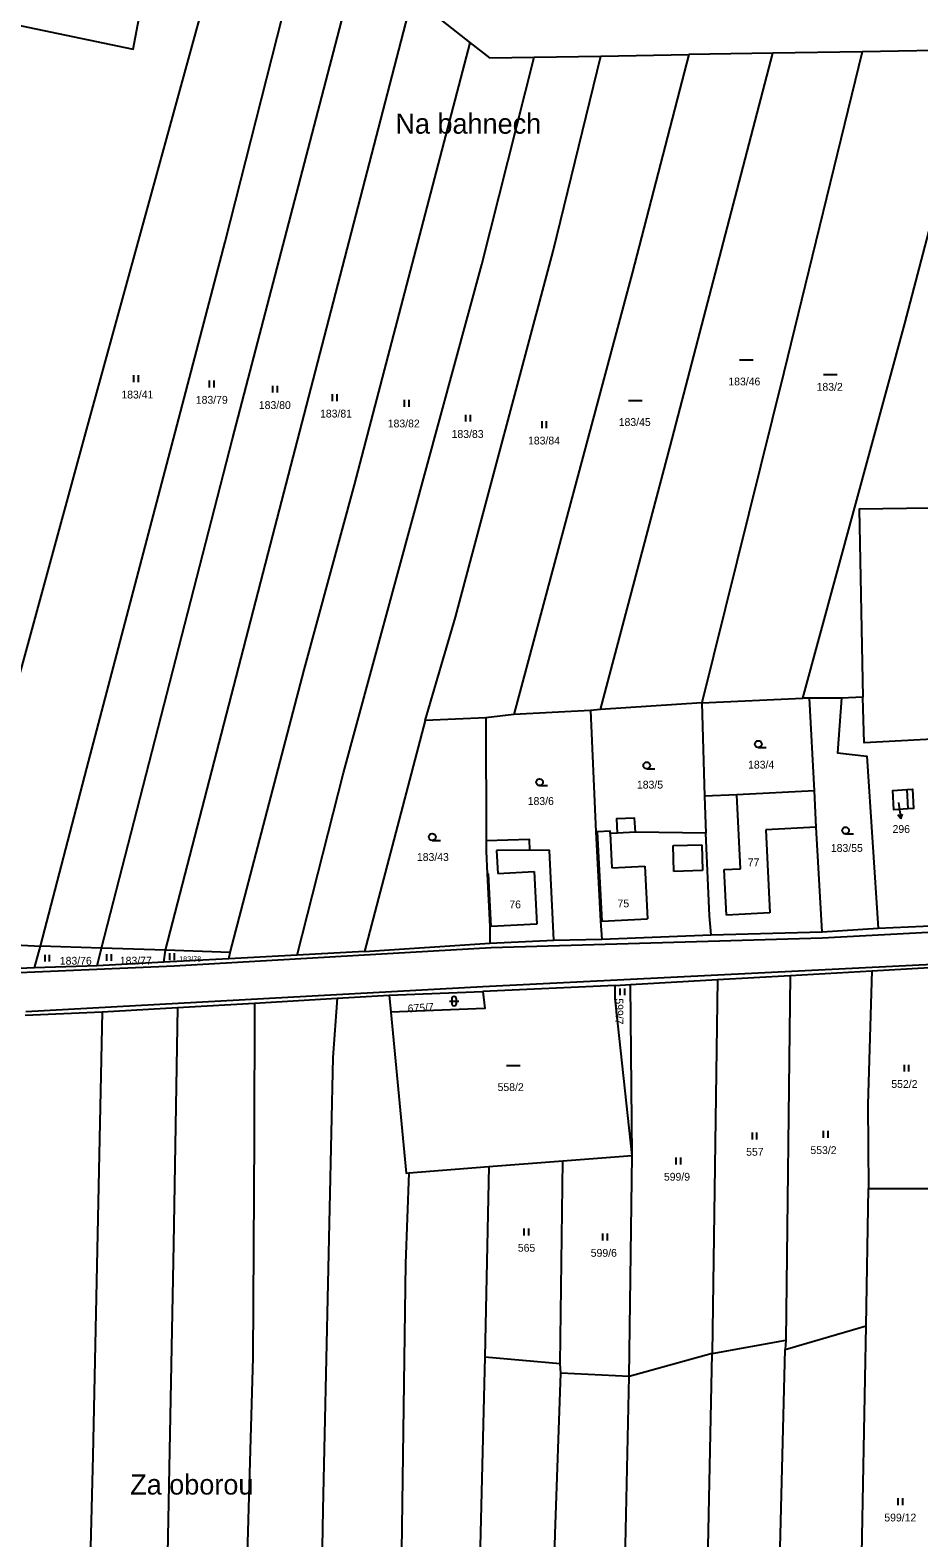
# Model space of a CAD drawing. Extents: x -747333 to -743907, y -1134120 to -1130051.
# Drawn here: x -747026.2 to -746832.8, y -1132407.1 to -1132079.1 of the extents above; entities that cross this region are included whole.
import ezdxf

# ---------------------------------------------------------------- set-up
doc = ezdxf.new("R2010")
doc.units = 0
for name, color, linetype in [('Hranice parcel', 7, 'Continuous'), ('Parcelní čísla', 7, 'Continuous'), ('Pop  PČ popisy', 7, 'Continuous'), ('Vnitřní kresba', 7, 'Continuous'), ('Značky kultur', 7, 'Continuous')]:
    doc.layers.add(name, color=color, linetype=linetype)

msp = doc.modelspace()

# ---------------------------------------------------------------- linework, layer by layer
at = {"layer": 'Hranice parcel'}
for p, q in [((-746942.98, -1132071.88), (-746930.38, -1132081.81)), ((-746916.47, -1132084.95), (-746901.96, -1132084.72)), ((-746901.96, -1132084.72), (-746882.82, -1132084.41)), ((-746864.54, -1132084.11), (-746882.82, -1132084.41)), ((-746845.06, -1132083.8), (-746864.54, -1132084.11)), ((-746820.24, -1132083.39), (-746845.06, -1132083.8)), ((-746879.98, -1132225.48), (-746902.04, -1132226.9)), ((-746879.98, -1132225.48), (-746858.02, -1132224.47)), ((-746879.98, -1132225.48), (-746879.44, -1132245.79)), ((-746856.57, -1132224.4), (-746858.02, -1132224.47)), ((-746849.62, -1132224.47), (-746856.57, -1132224.4)), ((-746855.47, -1132244.6), (-746856.57, -1132224.4)), ((-746844.91, -1132224.19), (-746849.62, -1132224.47)), ((-746940.23, -1132229.26), (-746953.39, -1132279.59)), ((-746927.02, -1132228.69), (-746940.23, -1132229.26)), ((-746920.89, -1132228), (-746927.02, -1132228.69)), ((-746927.02, -1132228.69), (-746926.95, -1132255.46)), ((-746904.25, -1132227.12), (-746920.89, -1132228)), ((-746902.04, -1132226.9), (-746904.25, -1132227.12)), ((-746904.25, -1132227.12), (-746903.04, -1132253.55)), ((-746879.44, -1132245.79), (-746879.09, -1132253.81)), ((-746926.95, -1132255.46), (-746926.94, -1132257.7)), ((-746903.04, -1132253.55), (-746902.06, -1132272.95)), ((-746879.09, -1132253.81), (-746894.45, -1132253.61)), ((-746926.15, -1132274.1), (-746926.09, -1132277.74)), ((-746902.06, -1132272.95), (-746901.75, -1132276.88)), ((-746877.98, -1132275.95), (-746853.79, -1132275.31)), ((-746853.79, -1132275.31), (-746841.63, -1132274.45)), ((-746841.63, -1132274.45), (-746801.64, -1132272.79)), ((-747044.43, -1132277.24), (-747023.94, -1132278.4)), ((-747025.21, -1132283.12), (-747023.94, -1132278.4)), ((-747010.67, -1132278.83), (-747023.94, -1132278.4)), ((-747011.61, -1132282.68), (-747010.67, -1132278.83)), ((-746996.68, -1132279.26), (-747010.67, -1132278.83)), ((-746953.39, -1132279.59), (-746926.09, -1132277.74)), ((-746926.09, -1132277.74), (-746912.17, -1132277.09)), ((-746912.17, -1132277.09), (-746901.75, -1132276.88)), ((-746901.75, -1132276.88), (-746877.98, -1132275.95)), ((-746997.1, -1132281.91), (-747011.61, -1132282.68)), ((-746997.1, -1132281.91), (-746996.68, -1132279.26)), ((-746982.92, -1132281.16), (-746997.1, -1132281.91)), ((-746982.63, -1132279.76), (-746996.68, -1132279.26)), ((-746982.92, -1132281.16), (-746982.63, -1132279.76)), ((-746968.03, -1132280.37), (-746982.92, -1132281.16)), ((-746953.39, -1132279.59), (-746968.03, -1132280.37)), ((-747025.21, -1132283.12), (-747046, -1132283.98)), ((-747011.61, -1132282.68), (-747025.21, -1132283.12)), ((-746876.61, -1132285.67), (-746860.79, -1132284.76)), ((-746860.79, -1132284.76), (-746861.69, -1132364.09)), ((-746860.79, -1132284.76), (-746843.01, -1132283.74)), ((-746843.01, -1132283.74), (-746826.69, -1132282.8)), ((-746948.06, -1132289.05), (-746927.67, -1132288.23)), ((-746898.83, -1132286.94), (-746927.67, -1132288.23)), ((-746898.83, -1132286.94), (-746895.48, -1132286.75)), ((-746895.48, -1132286.75), (-746876.61, -1132285.67)), ((-746895.12, -1132323.92), (-746895.48, -1132286.75)), ((-746876.61, -1132285.67), (-746877.7, -1132367.03)), ((-747010.5, -1132292.69), (-746994.07, -1132291.76)), ((-746994.07, -1132291.76), (-746977.35, -1132290.83)), ((-746977.35, -1132290.83), (-746959.35, -1132289.69)), ((-746959.35, -1132289.69), (-746948.06, -1132289.05)), ((-746948.06, -1132289.05), (-746947.65, -1132292.79)), ((-747027.28, -1132293.41), (-747010.5, -1132292.69)), ((-746910.26, -1132325.11), (-746895.12, -1132323.92)), ((-746895.83, -1132372.03), (-746895.12, -1132323.92)), ((-746943.76, -1132327.73), (-746926.33, -1132326.33)), ((-746926.33, -1132326.33), (-746927.19, -1132367.73)), ((-746926.33, -1132326.33), (-746910.26, -1132325.11)), ((-746910.84, -1132369.17), (-746910.26, -1132325.11)), ((-746844.2, -1132361.04), (-746843.71, -1132331.14)), ((-746843.71, -1132331.14), (-746827.45, -1132331.11)), ((-746861.83, -1132366.16), (-746844.2, -1132361.04)), ((-746877.7, -1132367.03), (-746861.69, -1132364.09)), ((-746861.69, -1132364.09), (-746861.83, -1132366.16)), ((-746877.7, -1132367.03), (-746895.83, -1132372.03)), ((-746927.19, -1132367.73), (-746910.84, -1132369.17)), ((-746910.7, -1132371.31), (-746910.84, -1132369.17)), ((-746895.83, -1132372.03), (-746910.7, -1132371.31))]:
    msp.add_line(p, q, dxfattribs=at)
for points in [[(-747023.94, -1132278.4), (-747013.85, -1132239.65), (-746995.01, -1132168), (-746983.73, -1132125.17), (-746965.7, -1132053.97)], [(-746983.8, -1132056.28), (-747014.12, -1132166.6), (-747033.2, -1132236.24)], [(-747029.81, -1132077.77), (-747003.78, -1132083.21), (-746998.74, -1132056.7)], [(-747010.67, -1132278.83), (-746982.16, -1132168), (-746954.65, -1132062.68)], [(-746996.68, -1132279.26), (-746973.89, -1132190.98), (-746953.76, -1132113.62), (-746942.98, -1132071.88)], [(-746982.63, -1132279.76), (-746966.54, -1132218.25), (-746955.56, -1132178), (-746930.38, -1132081.81)], [(-746930.38, -1132081.81), (-746926.2, -1132085.11), (-746916.47, -1132084.95)], [(-746968.03, -1132280.37), (-746957.98, -1132240.67), (-746927.88, -1132130.04), (-746916.47, -1132084.95)], [(-746940.23, -1132229.26), (-746933.58, -1132206.84), (-746912.31, -1132127.19), (-746901.96, -1132084.72)], [(-746882.82, -1132084.41), (-746895.12, -1132131.95), (-746920.89, -1132228)], [(-746902.04, -1132226.9), (-746886.87, -1132169.67), (-746864.54, -1132084.11)], [(-746845.06, -1132083.8), (-746862.13, -1132153.61), (-746879.98, -1132225.48)], [(-746858.02, -1132224.47), (-746835.83, -1132142.89), (-746820.24, -1132083.39)], [(-746825.13, -1132182.99), (-746845.75, -1132183.3), (-746844.91, -1132224.19)], [(-746849.62, -1132224.47), (-746850.48, -1132236.32), (-746844.05, -1132237.04), (-746841.63, -1132274.45)], [(-746794.52, -1132231.47), (-746844.62, -1132234.18), (-746844.91, -1132224.19)], [(-746855.47, -1132244.6), (-746872.39, -1132245.44), (-746879.44, -1132245.79)], [(-746853.79, -1132275.31), (-746855.08, -1132252.52), (-746855.47, -1132244.6)], [(-746835.13, -1132248.54), (-746838.17, -1132248.72), (-746838.41, -1132244.5), (-746835.37, -1132244.32), (-746834.14, -1132244.25), (-746833.89, -1132248.47), (-746835.13, -1132248.54)], [(-746894.45, -1132253.61), (-746894.61, -1132250.52), (-746898.59, -1132250.72), (-746898.44, -1132253.81), (-746899.93, -1132253.89), (-746899.95, -1132253.39), (-746902.74, -1132253.53), (-746903.04, -1132253.55)], [(-746912.17, -1132277.09), (-746913.17, -1132257.6), (-746917.39, -1132257.53), (-746917.46, -1132255.18), (-746926.95, -1132255.46)], [(-746877.98, -1132275.95), (-746878.29, -1132271.82), (-746879.09, -1132253.81)], [(-746926.94, -1132257.7), (-746926.7, -1132262.67), (-746926.15, -1132274.1)], [(-746843.01, -1132283.74), (-746843.82, -1132312.84), (-746843.71, -1132331.14)], [(-746927.67, -1132288.23), (-746927.23, -1132291.94), (-746947.65, -1132292.79)], [(-746895.12, -1132323.92), (-746898.83, -1132289.8), (-746898.83, -1132286.94)], [(-746994.07, -1132291.76), (-746995.01, -1132343.27), (-746997.51, -1132474.32), (-747001.71, -1132657.34), (-747003.26, -1132672.11)], [(-746977.35, -1132290.83), (-746977.44, -1132319.92), (-746977.72, -1132367.88), (-746979.85, -1132443.55), (-746982.29, -1132553.18), (-746985.61, -1132669.47)], [(-746959.35, -1132289.69), (-746960.3, -1132302.64), (-746962.44, -1132400.99), (-746964.87, -1132537.18), (-746967.72, -1132646.53), (-746969.06, -1132674.89)], [(-747010.5, -1132292.69), (-747012.54, -1132389.31), (-747014.17, -1132454.62), (-747017.56, -1132654.05), (-747018.91, -1132685.59)], [(-746947.65, -1132292.79), (-746944.36, -1132327.78), (-746943.76, -1132327.73)], [(-746943.76, -1132327.73), (-746944.46, -1132347.46), (-746945.61, -1132430.86), (-746948.6, -1132536.31), (-746950.31, -1132614.71), (-746953.98, -1132728.97)], [(-746848.38, -1132516.35), (-746848.19, -1132509.36), (-746845.99, -1132452.68), (-746844.2, -1132361.04)], [(-746883.71, -1132641.43), (-746882.26, -1132580.29), (-746880.26, -1132489.65), (-746877.7, -1132367.03)], [(-746867.07, -1132581.87), (-746866.39, -1132570.29), (-746866.75, -1132530.39), (-746865.89, -1132508.05), (-746863.33, -1132423.69), (-746861.83, -1132366.16)], [(-746927.19, -1132367.73), (-746928.41, -1132414.86), (-746930.5, -1132480.45), (-746932.76, -1132558.86), (-746933.47, -1132639.7), (-746936.07, -1132726.06)], [(-746919.52, -1132723.37), (-746917.95, -1132661.55), (-746916.52, -1132580.59), (-746911.94, -1132406.26), (-746910.7, -1132371.31)], [(-746902.27, -1132701.95), (-746900.26, -1132612.11), (-746897.97, -1132472.09), (-746895.83, -1132372.03)]]:
    msp.add_lwpolyline(points, dxfattribs=at)
at = {"layer": 'Pop  PČ popisy'}
for p, q in [((-746837.2, -1132247.17), (-746837.11, -1132247.75)), ((-746837.11, -1132247.75), (-746836.692, -1132250.722)), ((-746836.692, -1132250.722), (-746837.328, -1132249.8)), ((-746836.692, -1132250.722), (-746836.336, -1132249.66))]:
    msp.add_line(p, q, dxfattribs=at)
at = {"layer": 'Vnitřní kresba'}
for p, q in [((-746871.59, -1132261.57), (-746872.39, -1132245.44)), ((-746835.37, -1132244.32), (-746835.13, -1132248.54)), ((-746855.08, -1132252.52), (-746866.06, -1132253.06)), ((-746902.74, -1132253.53), (-746901.76, -1132272.93)), ((-746899.93, -1132253.89), (-746899.55, -1132261.35)), ((-746894.45, -1132253.61), (-746898.44, -1132253.81)), ((-746866.06, -1132253.06), (-746865.16, -1132271.17)), ((-746917.39, -1132257.53), (-746924.65, -1132257.59)), ((-746924.65, -1132257.59), (-746924.41, -1132262.56)), ((-746886.2, -1132256.46), (-746879.99, -1132256.32)), ((-746886.05, -1132262.18), (-746886.2, -1132256.46)), ((-746879.99, -1132256.32), (-746879.84, -1132261.96)), ((-746926.4, -1132262.66), (-746926.7, -1132262.67)), ((-746925.85, -1132274.09), (-746926.4, -1132262.66)), ((-746924.41, -1132262.56), (-746916.46, -1132262.18)), ((-746916.46, -1132262.18), (-746915.91, -1132273.61)), ((-746899.55, -1132261.35), (-746892.39, -1132260.99)), ((-746892.39, -1132260.99), (-746891.81, -1132272.43)), ((-746879.84, -1132261.96), (-746886.05, -1132262.18)), ((-746875.1, -1132261.74), (-746871.59, -1132261.57)), ((-746874.61, -1132271.64), (-746875.1, -1132261.74)), ((-746901.76, -1132272.93), (-746891.81, -1132272.43)), ((-746865.16, -1132271.17), (-746874.61, -1132271.64)), ((-746853.8, -1132276.58), (-746771.51, -1132272.22)), ((-746915.91, -1132273.61), (-746925.85, -1132274.09)), ((-746901.76, -1132272.93), (-746902.06, -1132272.95)), ((-746994.84, -1132282.65), (-746925.83, -1132278.65)), ((-746925.83, -1132278.65), (-746853.8, -1132276.58)), ((-746826.79, -1132282.23), (-746927.68, -1132287.24)), ((-747046.57, -1132284.9), (-746994.84, -1132282.65)), ((-746927.68, -1132287.24), (-747027.14, -1132292.69))]:
    msp.add_line(p, q, dxfattribs=at)
at = {"layer": 'Značky kultur'}
for p, q in [((-746871.808, -1132150.81), (-746868.808, -1132150.81)), ((-747003.611, -1132155.68), (-747003.611, -1132154.18)), ((-747002.61, -1132155.68), (-747002.61, -1132154.18)), ((-746853.508, -1132153.99), (-746850.508, -1132153.99)), ((-746987.131, -1132156.82), (-746987.131, -1132155.32)), ((-746986.13, -1132156.82), (-746986.13, -1132155.32)), ((-746973.331, -1132157.96), (-746973.331, -1132156.46)), ((-746972.33, -1132157.96), (-746972.33, -1132156.46)), ((-746960.341, -1132159.82), (-746960.341, -1132158.32)), ((-746959.34, -1132159.82), (-746959.34, -1132158.32)), ((-746944.701, -1132161.02), (-746944.701, -1132159.52)), ((-746943.7, -1132161.02), (-746943.7, -1132159.52)), ((-746895.958, -1132159.65), (-746892.958, -1132159.65)), ((-746931.321, -1132164.26), (-746931.321, -1132162.76)), ((-746930.32, -1132164.26), (-746930.32, -1132162.76)), ((-746914.771, -1132165.68), (-746914.771, -1132164.18)), ((-746913.77, -1132165.68), (-746913.77, -1132164.18)), ((-746867.703, -1132235.19), (-746865.953, -1132235.19)), ((-746891.963, -1132239.83), (-746890.213, -1132239.83)), ((-746915.313, -1132243.47), (-746913.563, -1132243.47)), ((-746938.643, -1132255.39), (-746936.893, -1132255.39)), ((-746848.713, -1132253.98), (-746846.963, -1132253.98)), ((-747022.941, -1132281.76), (-747022.941, -1132280.26)), ((-747021.94, -1132281.76), (-747021.94, -1132280.26)), ((-747009.491, -1132281.61), (-747009.491, -1132280.11)), ((-747008.49, -1132281.61), (-747008.49, -1132280.11)), ((-746995.781, -1132281.45), (-746995.781, -1132279.95)), ((-746994.78, -1132281.45), (-746994.78, -1132279.95)), ((-746897.761, -1132289.08), (-746897.761, -1132287.58)), ((-746896.76, -1132289.08), (-746896.76, -1132287.58)), ((-746934.901, -1132290.371), (-746932.899, -1132290.371)), ((-746934.401, -1132289.871), (-746934.401, -1132290.872)), ((-746933.399, -1132290.872), (-746933.399, -1132289.871)), ((-746922.518, -1132304.36), (-746919.518, -1132304.36)), ((-746835.911, -1132305.69), (-746835.911, -1132304.19)), ((-746834.91, -1132305.69), (-746834.91, -1132304.19)), ((-746868.981, -1132320.45), (-746868.981, -1132318.95)), ((-746867.98, -1132320.45), (-746867.98, -1132318.95)), ((-746853.501, -1132320.08), (-746853.501, -1132318.58)), ((-746852.5, -1132320.08), (-746852.5, -1132318.58)), ((-746885.581, -1132325.87), (-746885.581, -1132324.37)), ((-746884.58, -1132325.87), (-746884.58, -1132324.37)), ((-746918.631, -1132341.33), (-746918.631, -1132339.83)), ((-746917.63, -1132341.33), (-746917.63, -1132339.83)), ((-746901.501, -1132342.43), (-746901.501, -1132340.93)), ((-746900.5, -1132342.43), (-746900.5, -1132340.93)), ((-746837.241, -1132400.02), (-746837.241, -1132398.52)), ((-746836.24, -1132400.02), (-746836.24, -1132398.52))]:
    msp.add_line(p, q, dxfattribs=at)
for centre in [(-746867.703, -1132234.44), (-746891.963, -1132239.08), (-746915.313, -1132242.72), (-746848.713, -1132253.23), (-746938.643, -1132254.64)]:
    msp.add_circle(centre, 0.75, dxfattribs=at)
for centre, start, end in [((-746933.9, -1132289.871), 0, 180), ((-746933.9, -1132290.871), 180, 359.98789)]:
    msp.add_arc(centre, 0.5, start, end, dxfattribs=at)

# ---------------------------------------------------------------- texts
at = {"layer": 'Parcelní čísla'}
for s, height, p in [('183/41', 1.7, (-747006.32, -1132159.23)), ('183/46', 1.7, (-746874.21, -1132156.38)), ('183/2', 1.7, (-746855, -1132157.54)), ('183/79', 1.7, (-746990.12, -1132160.37)), ('183/80', 1.7, (-746976.4, -1132161.51)), ('183/81', 1.7, (-746963.08, -1132163.37)), ('183/82', 1.7, (-746948.34, -1132165.52)), ('183/45', 1.7, (-746898.07, -1132165.21)), ('183/83', 1.7, (-746934.44, -1132167.81)), ('183/84', 1.7, (-746917.81, -1132169.23)), ('183/4', 1.7, (-746869.92, -1132239.75)), ('183/5', 1.7, (-746894.11, -1132244.1)), ('183/6', 1.7, (-746917.88, -1132247.67)), ('296', 1.7, (-746838.474, -1132253.76)), ('183/55', 1.7, (-746851.9, -1132257.88)), ('183/43', 1.7, (-746942, -1132259.85)), ('77', 1.7, (-746869.99, -1132261.02)), ('76', 1.7, (-746921.88, -1132270.16)), ('75', 1.7, (-746898.33, -1132269.95)), ('183/76', 1.7, (-747019.72, -1132282.42)), ('183/77', 1.7, (-747006.65, -1132282.4)), ('183/78', 1.14, (-746993.76, -1132281.76)), ('558/2', 1.7, (-746924.44, -1132309.92)), ('552/2', 1.7, (-746838.74, -1132309.24)), ('557', 1.7, (-746870.34, -1132324)), ('553/2', 1.7, (-746856.35, -1132323.63)), ('599/9', 1.7, (-746888.24, -1132329.42)), ('565', 1.7, (-746920.03, -1132344.88)), ('599/6', 1.7, (-746904.16, -1132345.98)), ('599/12', 1.7, (-746840.26, -1132403.57))]:
    msp.add_text(s, height=height, dxfattribs=at).set_placement(p)
for s, rotation, p in [('675/7', 4, (-746943.94, -1132292.847)), ('599/7', 270, (-746898.79, -1132289.75))]:
    msp.add_text(s, height=1.7, rotation=rotation, dxfattribs=at).set_placement(p)
at = {"layer": 'Pop  PČ popisy'}
for s, p in [('Na bahnech', (-746946.678, -1132101.62)), ('Za oborou', (-747004.402, -1132397.72))]:
    msp.add_text(s, height=4.4, dxfattribs=at).set_placement(p)

doc.saveas('drawing.dxf')
